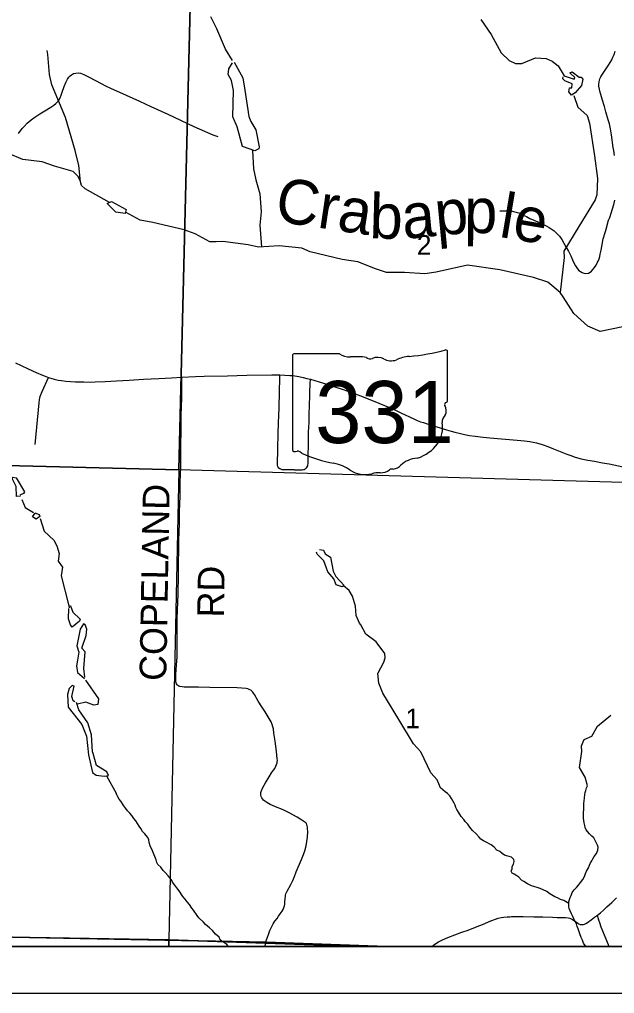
# Model space of a CAD drawing. Extents: x 0 to 34, y 0 to 22.
# Drawn here: x 3.798 to 5.063, y 13.5 to 15.568 of the extents above; entities that cross this region are included whole.
import ezdxf

# ---------------------------------------------------------------- set-up
doc = ezdxf.new("R2010")
doc.units = 0
for name, color, linetype in [('GM_X_Corporation', 7, 'Continuous'), ('GM_X_Minor_River', 7, 'Continuous'), ('GM_X_Minor_River_Text', 7, 'Continuous'), ('GM_X_Section_Text', 7, 'Continuous'), ('GM_X_State_Location', 7, 'Continuous'), ('GM_X_State_Route', 7, 'Continuous'), ('GM_X_State_Shield', 7, 'Continuous'), ('GM_X_Township_Road', 7, 'Continuous'), ('GM_X_Township_Road_Text', 7, 'Continuous'), ('SH_Data', 7, 'Continuous')]:
    doc.layers.add(name, color=color, linetype=linetype)

msp = doc.modelspace()

# ---------------------------------------------------------------- linework, layer by layer
at = {"layer": 'GM_X_Corporation'}
for points in [[(2.6, 16.6918), (2.6, 13.6), (9.4, 13.6), (9.4, 16.4853), (9.09, 16.4927), (8.0963, 16.5226), (6.2194, 16.578), (6.0834, 16.5816), (5.4202, 16.5982), (4.6351, 16.6229), (4.5473, 16.6256), (4.1867, 16.6352), (4.1011, 16.6362), (4.0515, 16.6368), (3.1684, 16.6682), (3.1555, 16.6686)], [(4.1616, 15.6255), (4.1372, 14.6117), (3.1218, 14.6372), (3.1435, 15.6571)], [(5.1793, 15.5873), (5.155, 14.5827), (4.1372, 14.6117), (4.1616, 15.6255)], [(3.1218, 14.6372), (4.1372, 14.6117), (4.1159, 13.6143), (3.1037, 13.6311)], [(4.5265, 13.6), (5.1312, 13.6), (5.155, 14.5827), (4.1372, 14.6117), (4.1159, 13.6143)], [(2.6, 13.6417), (2.6, 13.6), (4.5781, 13.6), (4.3222, 13.6092), (3.3525, 13.6282), (3.2812, 13.6297), (3.1025, 13.6315), (3.0575, 13.6324)], [(3.0626, 13.6), (4.1154, 13.6), (4.1159, 13.6143), (3.1037, 13.6311), (3.0633, 13.6314)], [(4.1154, 13.6), (4.5265, 13.6), (4.1159, 13.6143)]]:
    msp.add_lwpolyline(points, close=True, dxfattribs=at)
msp.add_lwpolyline([(3.1555, 16.6686), (3.148, 15.8071), (3.1401, 15.483), (3.1263, 14.9513), (3.1142, 14.3277), (3.1134, 14.2853), (3.1127, 14.2486), (3.1121, 14.2169), (3.109, 14.0614), (3.1089, 14.0542), (3.1033, 13.7653), (3.1025, 13.6315), (3.2812, 13.6297), (3.3525, 13.6282), (4.3222, 13.6092), (4.5781, 13.6), (9.4, 13.6)], dxfattribs=at)
at = {"layer": 'GM_X_Minor_River'}
for points in [[(4.2507, 15.481), (4.2363, 15.505), (4.2174, 15.548), (4.2049, 15.5736)], [(4.7788, 15.5683), (4.8005, 15.536), (4.8219, 15.4972), (4.8385, 15.4808), (4.8522, 15.4749), (4.8659, 15.4748), (4.8949, 15.4866), (4.917, 15.4854), (4.93, 15.4799), (4.9426, 15.4698), (4.9555, 15.4484)], [(3.9896, 15.1797), (3.9378, 15.2084), (3.9305, 15.2155), (3.9278, 15.2231), (3.9242, 15.2579), (3.9169, 15.29), (3.8961, 15.3602), (3.8674, 15.4292), (3.8625, 15.4515), (3.8589, 15.4939), (3.8569, 15.5022)], [(4.2545, 15.4773), (4.2729, 15.4442), (4.277, 15.4181), (4.2854, 15.3625), (4.2902, 15.3512), (4.3007, 15.3339), (4.3076, 15.2976), (4.307, 15.2934), (4.2983, 15.2891), (4.2724, 15.2982), (4.2611, 15.3405), (4.2517, 15.3612), (4.2531, 15.4173), (4.2486, 15.4389), (4.2416, 15.4513), (4.2434, 15.4634), (4.2511, 15.4764)], [(4.9555, 15.4488), (4.9768, 15.4411), (4.9783, 15.4453), (4.9679, 15.4546), (4.9724, 15.4573), (4.9874, 15.4454), (4.9919, 15.4455), (4.9954, 15.4414), (4.9922, 15.4277), (4.9791, 15.4123), (4.9712, 15.4073), (4.9654, 15.4148), (4.9672, 15.4231), (4.9718, 15.4232), (4.9728, 15.4312), (4.9568, 15.4378), (4.9529, 15.4419), (4.9532, 15.4465)], [(4.9758, 15.407), (4.9849, 15.3821), (5.0045, 15.3645), (5.0097, 15.3483), (5.0202, 15.2783), (5.0266, 15.2303), (5.0248, 15.1958), (5.0212, 15.1851), (4.9867, 15.1285), (4.9545, 15.0761), (4.9555, 15.0628), (4.9469, 14.9884)], [(3.9275, 15.2253), (3.9234, 15.2347), (3.9122, 15.2456), (3.873, 15.2568), (3.8467, 15.2658), (3.8056, 15.2709), (3.7751, 15.2838)], [(4.2933, 15.2902), (4.2954, 15.2508), (4.3007, 15.2277), (4.3087, 15.1979), (4.3116, 15.16), (4.309, 15.1315), (4.3126, 15.0852)], [(3.9846, 15.1776), (3.994, 15.1816), (4.025, 15.1649), (4.0229, 15.1562), (4.0031, 15.1593), (3.9846, 15.1776)], [(5.0805, 14.9159), (5.0321, 14.9058), (5.0058, 14.9172), (4.9762, 14.9441), (4.9533, 14.9794), (4.9467, 14.9888), (4.9206, 15.0104), (4.8904, 15.0205), (4.8188, 15.0366), (4.7504, 15.0462), (4.6838, 15.0316), (4.6592, 15.0282), (4.6167, 15.0306), (4.5783, 15.0308), (4.5524, 15.0395), (4.5478, 15.0417), (4.5173, 15.0534), (4.4838, 15.0586), (4.4157, 15.0747), (4.3985, 15.0828), (4.3498, 15.0874), (4.3062, 15.0849), (4.2845, 15.0895), (4.2305, 15.097), (4.2165, 15.0961), (4.2029, 15.0959), (4.1719, 15.1129), (4.1482, 15.1216), (4.0819, 15.1373), (4.0546, 15.1419), (4.0236, 15.1591)], [(3.8006, 14.5562), (3.7923, 14.5553), (3.7912, 14.5766), (3.7834, 14.5924), (3.7837, 14.5965), (3.7917, 14.5948), (3.8088, 14.5654), (3.807, 14.5616), (3.799, 14.5581)], [(3.8037, 14.5487), (3.8108, 14.5321), (3.828, 14.5214)], [(3.8307, 14.5203), (3.8399, 14.5174), (3.8418, 14.5128), (3.8339, 14.5074), (3.8259, 14.5122), (3.8315, 14.5199)], [(3.8427, 14.5087), (3.851, 14.4815), (3.8714, 14.4628), (3.878, 14.4504), (3.8825, 14.4346), (3.8808, 14.4179), (3.8901, 14.4055), (3.8869, 14.3872), (3.9034, 14.3234), (3.9043, 14.3189)], [(4.4356, 14.4426), (4.444, 14.4416), (4.4479, 14.4333), (4.4594, 14.4263), (4.4647, 14.3968), (4.4706, 14.3855), (4.488, 14.366), (4.4842, 14.3633), (4.4709, 14.368), (4.4665, 14.3805), (4.4534, 14.3955), (4.4451, 14.4189), (4.4308, 14.4327), (4.4296, 14.4372)], [(4.6927, 13.9368), (4.686, 13.9537), (4.6725, 13.9687), (4.651, 14.0131), (4.6352, 14.0304), (4.6045, 14.0815), (4.5703, 14.1378), (4.5616, 14.1593), (4.5594, 14.1794), (4.5727, 14.2038), (4.5756, 14.2126), (4.5747, 14.2217), (4.5561, 14.2464), (4.5343, 14.2628), (4.5233, 14.2827), (4.521, 14.2865), (4.5139, 14.3023), (4.5121, 14.3228), (4.5061, 14.3439), (4.4987, 14.3559), (4.4871, 14.3654)], [(3.9031, 14.3234), (3.9069, 14.3231), (3.9116, 14.3095), (3.9274, 14.2949), (3.9259, 14.2904), (3.9106, 14.278), (3.9067, 14.2825), (3.9023, 14.2953), (3.9031, 14.3177)], [(3.9372, 14.1715), (3.9354, 14.1904), (3.9379, 14.2253), (3.931, 14.2336), (3.9404, 14.2599), (3.9414, 14.2735), (3.9382, 14.2826), (3.9344, 14.2852), (3.9273, 14.2733), (3.9203, 14.2383), (3.9246, 14.2248), (3.9218, 14.208), (3.9194, 14.1955), (3.9215, 14.1819), (3.9365, 14.1688)], [(3.9163, 14.1196), (3.9125, 14.1215), (3.9093, 14.1305), (3.9143, 14.1526), (3.9101, 14.154), (3.9041, 14.1475), (3.9002, 14.1346), (3.9017, 14.108), (3.9311, 14.0709), (3.9405, 14.0464), (3.9453, 14.0071), (3.9538, 13.9693), (3.9611, 13.9637), (3.9782, 13.9613), (3.9873, 13.9629), (3.9842, 13.9705), (3.962, 13.9842), (3.9547, 14.0095), (3.9539, 14.0132), (3.9511, 14.0492), (3.9439, 14.0749), (3.9245, 14.1023), (3.9198, 14.1178)], [(3.9388, 14.1654), (3.9663, 14.1257), (3.9646, 14.1135), (3.9566, 14.1122), (3.9395, 14.1184), (3.9217, 14.1144)], [(5.005, 13.9412), (5.0002, 13.9594), (4.9881, 13.9797), (4.9929, 14.0136), (4.9924, 14.0261), (4.9982, 14.039), (5.0141, 14.0465), (5.0267, 14.0675), (5.0548, 14.0907)], [(3.9832, 13.9622), (4.0038, 13.9255)], [(5.0015, 13.6), (5.0002, 13.6017), (4.9967, 13.6066), (4.9944, 13.6134), (4.9913, 13.6191), (4.9885, 13.6266), (4.9866, 13.6331), (4.9854, 13.6372), (4.9834, 13.6422), (4.9815, 13.6478), (4.9784, 13.6543), (4.9764, 13.6588), (4.9737, 13.6637), (4.971, 13.6694), (4.9682, 13.6754), (4.9663, 13.6804), (4.9655, 13.6849), (4.9654, 13.6895), (4.9658, 13.6944), (4.9672, 13.6994), (4.9683, 13.7036), (4.9702, 13.7078), (4.9728, 13.7146), (4.9765, 13.72), (4.9818, 13.7253), (4.9863, 13.7303), (4.9901, 13.7357), (4.9949, 13.7418), (4.9987, 13.7487), (5.0009, 13.7548), (5.0031, 13.7597), (5.0072, 13.767), (5.0095, 13.7724), (5.0117, 13.7773), (5.0143, 13.7815), (5.0166, 13.7857), (5.0196, 13.7907), (5.024, 13.7976), (5.027, 13.8041), (5.0277, 13.8105), (5.0265, 13.8147), (5.0234, 13.8204), (5.0215, 13.8249), (5.0184, 13.8306), (5.0142, 13.8339), (5.0095, 13.8388), (5.0053, 13.8437), (5.0026, 13.8479), (5.0003, 13.8528), (4.9995, 13.857), (4.9983, 13.8627), (4.9974, 13.8676), (4.9966, 13.8721), (4.9965, 13.8835), (4.9972, 13.8915), (4.9971, 13.898), (4.9974, 13.9041), (4.9982, 13.9086), (4.9989, 13.9155), (4.9992, 13.9223), (4.9999, 13.9269), (5.0014, 13.9311), (5.0032, 13.9368), (5.005, 13.9412)], [(4.2427, 13.6), (4.2392, 13.6041), (4.2338, 13.6074), (4.2292, 13.6108), (4.225, 13.6142), (4.2223, 13.6198), (4.215, 13.6262), (4.2088, 13.6341), (4.2019, 13.6394), (4.1938, 13.6469), (4.1896, 13.6514), (4.1792, 13.6608), (4.1758, 13.6657), (4.168, 13.6767), (4.1646, 13.6812), (4.1595, 13.6888), (4.1549, 13.6948), (4.1507, 13.7001), (4.1457, 13.7061), (4.1375, 13.7178), (4.1345, 13.7219), (4.1283, 13.7299), (4.1233, 13.7363), (4.1213, 13.7412), (4.1144, 13.7499), (4.1086, 13.7563), (4.104, 13.7612), (4.0986, 13.7683), (4.0921, 13.774), (4.0905, 13.7781), (4.0889, 13.7842), (4.0807, 13.8027), (4.0764, 13.8133), (4.0741, 13.8209), (4.0729, 13.8262), (4.0713, 13.8315), (4.0647, 13.8394), (4.0601, 13.8439), (4.0559, 13.8503), (4.0524, 13.8556), (4.0489, 13.8613), (4.0458, 13.867), (4.0416, 13.8715), (4.0373, 13.8783), (4.0327, 13.8828), (4.0277, 13.8877), (4.0246, 13.893), (4.0204, 13.8986), (4.0134, 13.9084), (4.0099, 13.913), (4.0072, 13.9175), (4.0053, 13.9222), (4.0038, 13.9255)], [(4.9655, 13.6909), (4.9551, 13.6973), (4.9474, 13.6996), (4.9413, 13.7033), (4.936, 13.7055), (4.9287, 13.7096), (4.9233, 13.7134), (4.9187, 13.7164), (4.9042, 13.7231), (4.9, 13.7242), (4.8912, 13.7275), (4.8859, 13.7286), (4.8817, 13.7308), (4.8775, 13.7327), (4.8698, 13.7379), (4.8652, 13.7405), (4.8591, 13.7473), (4.8548, 13.7496), (4.8495, 13.7533), (4.8453, 13.7552), (4.8429, 13.7601), (4.8448, 13.7646), (4.8451, 13.7696), (4.8477, 13.7749), (4.8492, 13.7803), (4.8484, 13.7848), (4.8434, 13.7893), (4.8388, 13.7908), (4.8327, 13.7923), (4.8285, 13.7941), (4.8239, 13.7975), (4.8189, 13.8012), (4.8128, 13.8046), (4.807, 13.8106), (4.8005, 13.8159), (4.7898, 13.8211), (4.7844, 13.8241), (4.7787, 13.8274), (4.7748, 13.8323), (4.7683, 13.8391), (4.761, 13.8463), (4.7552, 13.8534), (4.751, 13.8595), (4.7452, 13.8651), (4.7421, 13.8696), (4.7367, 13.876), (4.7309, 13.8851), (4.7274, 13.8904), (4.7251, 13.8953), (4.7243, 13.8999), (4.722, 13.904), (4.7189, 13.9089), (4.7161, 13.9142), (4.7127, 13.9199), (4.7077, 13.9248), (4.7027, 13.9281), (4.6981, 13.9327), (4.6927, 13.9368)]]:
    msp.add_lwpolyline(points, dxfattribs=at)
at = {"layer": 'GM_X_State_Route'}
msp.add_lwpolyline([(3.7903, 14.8388), (3.8019, 14.8332), (3.8166, 14.8267), (3.834, 14.8189), (3.8476, 14.8129), (3.8567, 14.8092), (3.8598, 14.8081), (3.8648, 14.8065), (3.8722, 14.8043), (3.8809, 14.8024), (3.8877, 14.8013), (3.8968, 14.8002), (3.9065, 14.7994), (3.9173, 14.7989), (3.935, 14.7985), (3.9491, 14.7984), (3.9595, 14.7986), (3.9808, 14.7995), (4.0045, 14.8008), (4.0315, 14.8024), (4.0618, 14.8042), (4.0948, 14.806), (4.1217, 14.8072), (4.1435, 14.8084), (4.1726, 14.8098), (4.1911, 14.8107), (4.24, 14.8117), (4.2813, 14.8126), (4.3347, 14.8134), (4.3518, 14.8133), (4.3622, 14.8129), (4.3731, 14.8124), (4.3781, 14.8119), (4.3832, 14.8113), (4.392, 14.81), (4.401, 14.8082), (4.4092, 14.8062), (4.4165, 14.8042), (4.426, 14.8013), (4.4444, 14.7956), (4.4684, 14.7883), (4.4836, 14.7832), (4.5082, 14.7744), (4.5227, 14.769), (4.5497, 14.7585), (4.5619, 14.7532), (4.574, 14.7484), (4.5928, 14.7404), (4.6101, 14.7323), (4.618, 14.7286), (4.627, 14.7243), (4.6375, 14.7194), (4.6433, 14.717), (4.6504, 14.7141), (4.6564, 14.7121), (4.6624, 14.7101), (4.6713, 14.7072), (4.694, 14.7007), (4.7055, 14.6971), (4.7155, 14.6942), (4.7234, 14.6919), (4.7324, 14.6895), (4.7438, 14.6869), (4.7544, 14.6848), (4.7662, 14.6832), (4.7833, 14.6814), (4.7976, 14.6801), (4.8554, 14.675), (4.871, 14.6733), (4.8825, 14.6718), (4.897, 14.6689), (4.9091, 14.6656), (4.9207, 14.6618), (4.9328, 14.6568), (4.9505, 14.6496), (4.9615, 14.6451), (4.9694, 14.6422), (4.9791, 14.6389), (4.9913, 14.6356), (5.0055, 14.6327), (5.0202, 14.6301), (5.0368, 14.6269), (5.0514, 14.6244), (5.0811, 14.6185)], dxfattribs=at)
at = {"layer": 'GM_X_State_Shield'}
for p, q in [((4.3783, 14.8547), (4.3783, 14.6546)), ((4.478, 14.8582), (4.3815, 14.8582)), ((4.7078, 14.7584), (4.7078, 14.8631)), ((4.7078, 14.7585), (4.7078, 14.7584))]:
    msp.add_line(p, q, dxfattribs=at)
for centre, major_axis, start_param, end_param in [((4.382, 14.8551), (0.00382, 0), 1.712693, 3.28349), ((4.501, 14.8814), (0.037, 0), 4.042523, 4.731795), ((4.5133, 14.7458), (0.133, 0), 1.404758, 1.657858), ((4.5435, 14.8562), (0.0107, 0), 3.836095, 5.185415), ((4.5592, 14.833), (0.0222, 0), 0.950623, 2.079405), ((4.635, 14.797), (0.0703, 0), 1.699011, 2.107814), ((4.5904, 15.131), (0.3495, 0), 4.814394, 5.042369), ((4.7042, 14.8635), (0.00367, 0), 6.141152, 7.989035), ((4.5878, 14.8648), (0.0267, 0), 4.081561, 5.145723), ((4.707, 14.7507), (0.00568, 0), 1.883978, 3.671073), ((4.6709, 14.7375), (0.0341, 0), 5.934695, 6.695948), ((4.7039, 14.758), (0.00393, 0), 5.05454, 6.418171), ((4.721, 14.7146), (0.0248, 0), 2.387724, 3.262537), ((4.61, 14.7013), (0.0874, 0), 5.101752, 6.440018), ((4.3821, 14.6542), (0.00385, 0), 3.00124, 4.508301), ((4.3826, 14.6746), (0.0294, 0), 4.665946, 4.897461), ((4.3887, 14.643), (0.0106, 0), 0.519207, 1.627899), ((4.5225, 14.8228), (0.2524, 0), 4.195997, 4.488961), ((4.4472, 14.5647), (0.079, 0), 0.823519, 1.323587), ((4.6469, 14.5984), (0.0479, 0), 1.647645, 2.488434), ((4.5327, 14.6421), (0.0501, 0), 4.026481, 4.996735), ((4.5616, 14.5729), (0.0412, 0), 1.495662, 1.94098), ((4.5653, 14.6271), (0.0267, 0), 4.691044, 5.507374), ((4.5894, 14.6077), (0.00752, 0), 1.147584, 2.315152), ((4.5862, 14.6352), (0.0282, 0), 4.937069, 5.64225)]:
    msp.add_ellipse(centre, major_axis=major_axis, ratio=0.8, start_param=start_param, end_param=end_param, dxfattribs=at)
at = {"layer": 'GM_X_Township_Road'}
msp.add_line((4.3198, 13.6), (4.3201, 13.6014), dxfattribs=at)
for points in [[(5.0628, 15.2792), (5.0609, 15.2897), (5.0598, 15.2962), (5.0562, 15.3233), (5.0542, 15.3358), (5.0515, 15.3465), (5.0489, 15.3552), (5.0441, 15.3721), (5.0409, 15.3835), (5.0365, 15.3987), (5.0336, 15.4087), (5.0314, 15.4158), (5.0303, 15.4203), (5.0292, 15.4265), (5.0293, 15.4305), (5.0298, 15.435), (5.0307, 15.439), (5.0316, 15.4422), (5.0333, 15.4463), (5.0355, 15.4502), (5.0381, 15.454), (5.0498, 15.4713), (5.0534, 15.4767), (5.0565, 15.4822), (5.0592, 15.488), (5.0616, 15.4939), (5.0639, 15.5012)], [(3.7963, 15.3258), (3.8041, 15.3364), (3.8082, 15.3412), (3.8145, 15.3478), (3.8233, 15.3549), (3.8309, 15.3605), (3.8419, 15.3677), (3.8521, 15.3744), (3.8649, 15.3818), (3.8711, 15.386), (3.8759, 15.39), (3.8804, 15.3947), (3.8833, 15.3991), (3.8855, 15.4038), (3.8861, 15.4054), (3.8894, 15.414), (3.8936, 15.4259), (3.8968, 15.4342), (3.8983, 15.4374), (3.9004, 15.4414), (3.9035, 15.4457), (3.906, 15.4483), (3.909, 15.4508), (3.9133, 15.4531), (3.9178, 15.4543), (3.9233, 15.4546), (3.928, 15.4539), (3.9352, 15.4515), (3.9438, 15.4469), (3.9613, 15.438), (3.9814, 15.4273), (3.9929, 15.4216), (4.0111, 15.4136), (4.0536, 15.3946), (4.0774, 15.3837), (4.1133, 15.3672), (4.1688, 15.3412), (4.2095, 15.3234), (4.2198, 15.3195)], [(4.819, 15.1618), (4.8394, 15.1616), (4.8434, 15.1615), (4.8481, 15.1607), (4.8537, 15.1593), (4.859, 15.1575), (4.864, 15.1556), (4.8687, 15.153), (4.8752, 15.1495), (4.8825, 15.1456), (4.8908, 15.1417), (4.8993, 15.1384), (4.9072, 15.1353), (4.9158, 15.1309), (4.9236, 15.1264), (4.934, 15.1195), (4.9403, 15.1137), (4.9454, 15.108), (4.9503, 15.1012), (4.9547, 15.0929), (4.9597, 15.0841), (4.9645, 15.0765), (4.9698, 15.0663), (4.9731, 15.0575), (4.9766, 15.0503), (4.9797, 15.0448), (4.9838, 15.0384), (4.9869, 15.0355), (4.9905, 15.0327), (4.9941, 15.0307), (4.9975, 15.0295), (5.0008, 15.029), (5.007, 15.0298), (5.0106, 15.0315), (5.0133, 15.0337), (5.0171, 15.0381), (5.0197, 15.0416), (5.0233, 15.0468), (5.0258, 15.0511), (5.0276, 15.0549), (5.0296, 15.0597), (5.031, 15.0646), (5.0322, 15.0698), (5.0338, 15.0785), (5.036, 15.0904), (5.0384, 15.1026), (5.0431, 15.1183), (5.0445, 15.1228), (5.05, 15.1417), (5.0527, 15.1479), (5.0557, 15.1567), (5.0584, 15.166), (5.0607, 15.1754), (5.0633, 15.1847)], [(3.8319, 14.6656), (3.8401, 14.754), (3.8407, 14.761), (3.8414, 14.7642), (3.8421, 14.7675), (3.8431, 14.7699), (3.8465, 14.778), (3.8598, 14.8081)], [(4.3201, 13.6014), (4.3226, 13.6119), (4.325, 13.6195), (4.3273, 13.6255), (4.3304, 13.6338), (4.3339, 13.641), (4.3375, 13.6478), (4.341, 13.6533), (4.3455, 13.6596), (4.349, 13.6645), (4.3524, 13.6695), (4.3563, 13.675), (4.3583, 13.6786), (4.36, 13.6827), (4.3611, 13.686), (4.3619, 13.6896), (4.3623, 13.6935), (4.363, 13.7025), (4.3633, 13.7053), (4.3639, 13.7089), (4.3645, 13.7114), (4.3655, 13.7142), (4.367, 13.7171), (4.375, 13.7315), (4.3794, 13.7402), (4.3826, 13.7483), (4.3862, 13.7584), (4.3903, 13.768), (4.3933, 13.7746), (4.3974, 13.7843), (4.4018, 13.7954), (4.4047, 13.8033), (4.4076, 13.8137), (4.409, 13.8229), (4.4102, 13.832), (4.4108, 13.844), (4.4106, 13.8494), (4.4101, 13.8535), (4.4097, 13.856), (4.409, 13.8584), (4.4079, 13.8607), (4.4064, 13.8624), (4.4043, 13.8641), (4.3985, 13.8682), (4.3886, 13.8741), (4.3713, 13.8838), (4.3614, 13.8885), (4.3537, 13.892), (4.346, 13.895), (4.3409, 13.897), (4.3313, 13.9013), (4.3276, 13.9032), (4.3236, 13.9057), (4.3199, 13.9085), (4.3171, 13.9107), (4.3144, 13.9136), (4.313, 13.9157), (4.3119, 13.9184), (4.3113, 13.9215), (4.3111, 13.9244), (4.3114, 13.9267), (4.312, 13.9291), (4.3155, 13.9371), (4.3209, 13.9471), (4.3285, 13.9604), (4.3338, 13.9683), (4.338, 13.9739), (4.3407, 13.9781), (4.3433, 13.9829), (4.3447, 13.9861), (4.3457, 13.9895), (4.346, 13.9918), (4.3463, 13.9953), (4.3462, 13.9984), (4.3444, 14.014), (4.3415, 14.0356), (4.339, 14.0528), (4.3379, 14.0618), (4.3369, 14.0664), (4.3353, 14.0713), (4.333, 14.0769), (4.3292, 14.084), (4.3202, 14.0981), (4.3134, 14.1085), (4.3057, 14.1207), (4.2974, 14.1348), (4.2956, 14.1377), (4.2941, 14.1397), (4.292, 14.142), (4.2898, 14.1438), (4.2867, 14.1457), (4.2838, 14.1467), (4.2798, 14.1476), (4.2709, 14.1483), (4.2612, 14.1487), (4.2025, 14.1496), (4.1789, 14.1504), (4.1561, 14.1506), (4.1483, 14.1506), (4.1438, 14.151), (4.1392, 14.152), (4.1369, 14.1528), (4.1351, 14.154), (4.1334, 14.1556), (4.1322, 14.1575), (4.1313, 14.1595), (4.1308, 14.1616), (4.1306, 14.1637), (4.1305, 14.1719), (4.1307, 14.1779), (4.1318, 14.1971), (4.1331, 14.215), (4.1336, 14.232), (4.1337, 14.2466), (4.1334, 14.268), (4.1336, 14.2953), (4.134, 14.315), (4.1355, 14.3476), (4.1358, 14.3617), (4.1359, 14.3757), (4.1362, 14.3994), (4.1364, 14.416), (4.1367, 14.4397), (4.1371, 14.4632), (4.1374, 14.479), (4.1382, 14.4996), (4.1386, 14.5223), (4.1393, 14.5412), (4.1395, 14.5548), (4.1396, 14.571), (4.1399, 14.5832), (4.1406, 14.6055), (4.1409, 14.6141), (4.141, 14.6325), (4.1414, 14.6642), (4.1417, 14.6961), (4.1418, 14.7103), (4.1419, 14.7182), (4.1422, 14.7272), (4.143, 14.7642), (4.1433, 14.7781), (4.1435, 14.7896), (4.1435, 14.8084)], [(4.3822, 14.6117), (4.367, 14.6116), (4.3582, 14.6119), (4.3563, 14.6122), (4.3537, 14.613), (4.3513, 14.6139), (4.3496, 14.6152), (4.348, 14.6173), (4.3471, 14.6191), (4.3466, 14.6218), (4.3465, 14.6276), (4.347, 14.6523), (4.3471, 14.6574), (4.3479, 14.6881), (4.3486, 14.7118), (4.3491, 14.7272), (4.3498, 14.7433), (4.3507, 14.7781), (4.3516, 14.806), (4.3518, 14.8133)], [(4.3822, 14.6117), (4.3929, 14.6119), (4.399, 14.612), (4.4015, 14.6123), (4.4036, 14.6128), (4.4055, 14.6138), (4.4069, 14.6149), (4.4081, 14.6159), (4.4098, 14.6183), (4.4107, 14.6207), (4.4113, 14.6228), (4.4115, 14.6256), (4.4122, 14.682), (4.4127, 14.6922), (4.4131, 14.7022), (4.4135, 14.7121), (4.4138, 14.7255), (4.4141, 14.7353), (4.4143, 14.7436), (4.4146, 14.7541), (4.415, 14.7642), (4.4154, 14.7769), (4.4161, 14.7945), (4.4165, 14.8042)], [(5.0265, 13.6666), (5.0325, 13.6716), (5.0389, 13.6773), (5.0464, 13.684), (5.0569, 13.6936), (5.067, 13.7031)], [(4.6741, 13.6), (4.6807, 13.6046), (4.6886, 13.6096), (4.6969, 13.6142), (4.7086, 13.6192), (4.7382, 13.6302), (4.7515, 13.6348), (4.767, 13.6406), (4.7856, 13.6479), (4.7965, 13.6527), (4.8021, 13.655), (4.8095, 13.658), (4.8155, 13.6598), (4.822, 13.6612), (4.8277, 13.6621), (4.8342, 13.6628), (4.8398, 13.6631), (4.844, 13.6634), (4.8579, 13.6635), (4.8683, 13.6635), (4.8911, 13.663), (4.9006, 13.6628), (4.9104, 13.6626), (4.931, 13.6619), (4.9407, 13.6616), (4.9581, 13.6614), (4.9642, 13.6607), (4.9675, 13.6599), (4.9704, 13.6586), (4.9732, 13.657), (4.9775, 13.6545), (4.9847, 13.6492), (4.9862, 13.6483), (4.9881, 13.6474), (4.9897, 13.6468), (4.9915, 13.6464), (4.993, 13.6463), (4.9946, 13.6464), (4.9965, 13.6468), (4.9986, 13.6475), (5.0017, 13.6489), (5.0054, 13.651), (5.0131, 13.6565), (5.0201, 13.6618), (5.0265, 13.6666)], [(5.0511, 13.6), (5.041, 13.6241), (5.034, 13.6407), (5.0311, 13.6499), (5.0294, 13.6559), (5.0281, 13.6604), (5.0265, 13.6666)]]:
    msp.add_lwpolyline(points, dxfattribs=at)
at = {"layer": 'SH_Data'}
for points in [[(2.5, 20.5), (9.5, 20.5), (9.5, 13.5), (2.5, 13.5)], [(2.6, 20.4), (9.4, 20.4), (9.4, 13.6), (2.6, 13.6)]]:
    msp.add_lwpolyline(points, close=True, dxfattribs=at)

# ---------------------------------------------------------------- texts
at = {"layer": 'GM_X_Minor_River_Text'}
for s, rotation, p in [('Cra', 351.4517, (4.3386, 15.1403)), ('b', 358.4484, (4.5412, 15.1037)), ('le', 350.4508, (4.8152, 15.1069)), ('ap', 5.4453, (4.6146, 15.1019)), ('p', 359.4474, (4.7427, 15.115))]:
    msp.add_text(s, height=0.0947, rotation=rotation, dxfattribs=at).set_placement(p)
at = {"layer": 'GM_X_Section_Text'}
for s, p in [('2', (4.6425, 15.0685)), ('1', (4.6183, 14.0632))]:
    msp.add_text(s, height=0.0419, rotation=0, dxfattribs=at).set_placement(p)
at = {"layer": 'GM_X_State_Location'}
msp.add_text('331', height=0.000189, rotation=0, dxfattribs=at).set_placement((4.4725, 14.7276))
for s in ['s', 'r']:
    msp.add_text(s, height=0.000189, dxfattribs=at).set_placement((4.5393, 14.7413))
at = {"layer": 'GM_X_State_Shield'}
msp.add_text('331', height=0.13184, dxfattribs=at).set_placement((4.4268, 14.6687))
at = {"layer": 'GM_X_Township_Road_Text'}
for s, rotation, p in [('COPELAND', 88.9678, (4.1101, 14.1635)), ('RD', 89.0128, (4.2326, 14.2981))]:
    msp.add_text(s, height=0.05682, rotation=rotation, dxfattribs=at).set_placement(p)

doc.saveas('drawing.dxf')
